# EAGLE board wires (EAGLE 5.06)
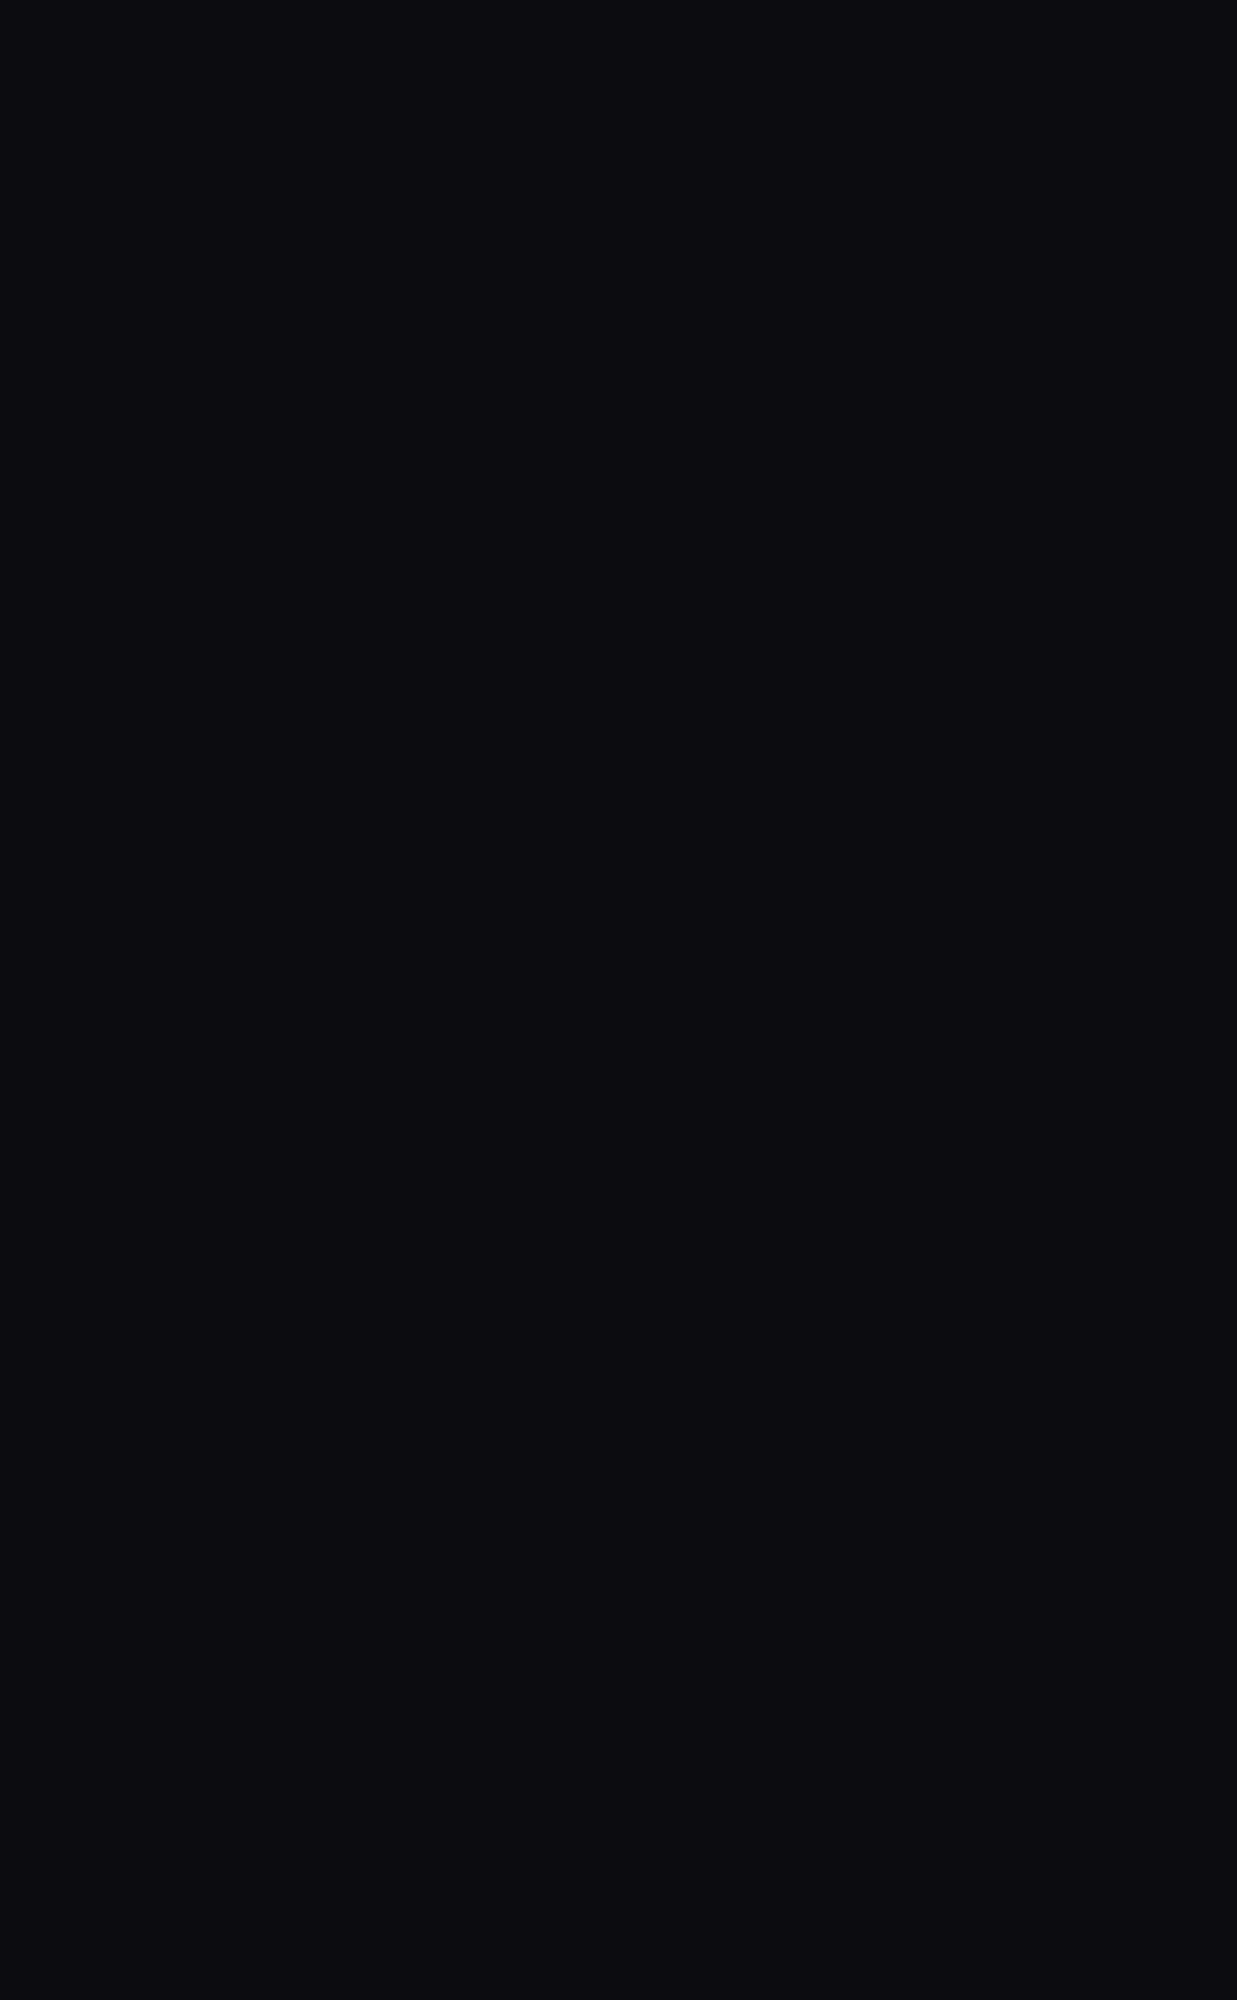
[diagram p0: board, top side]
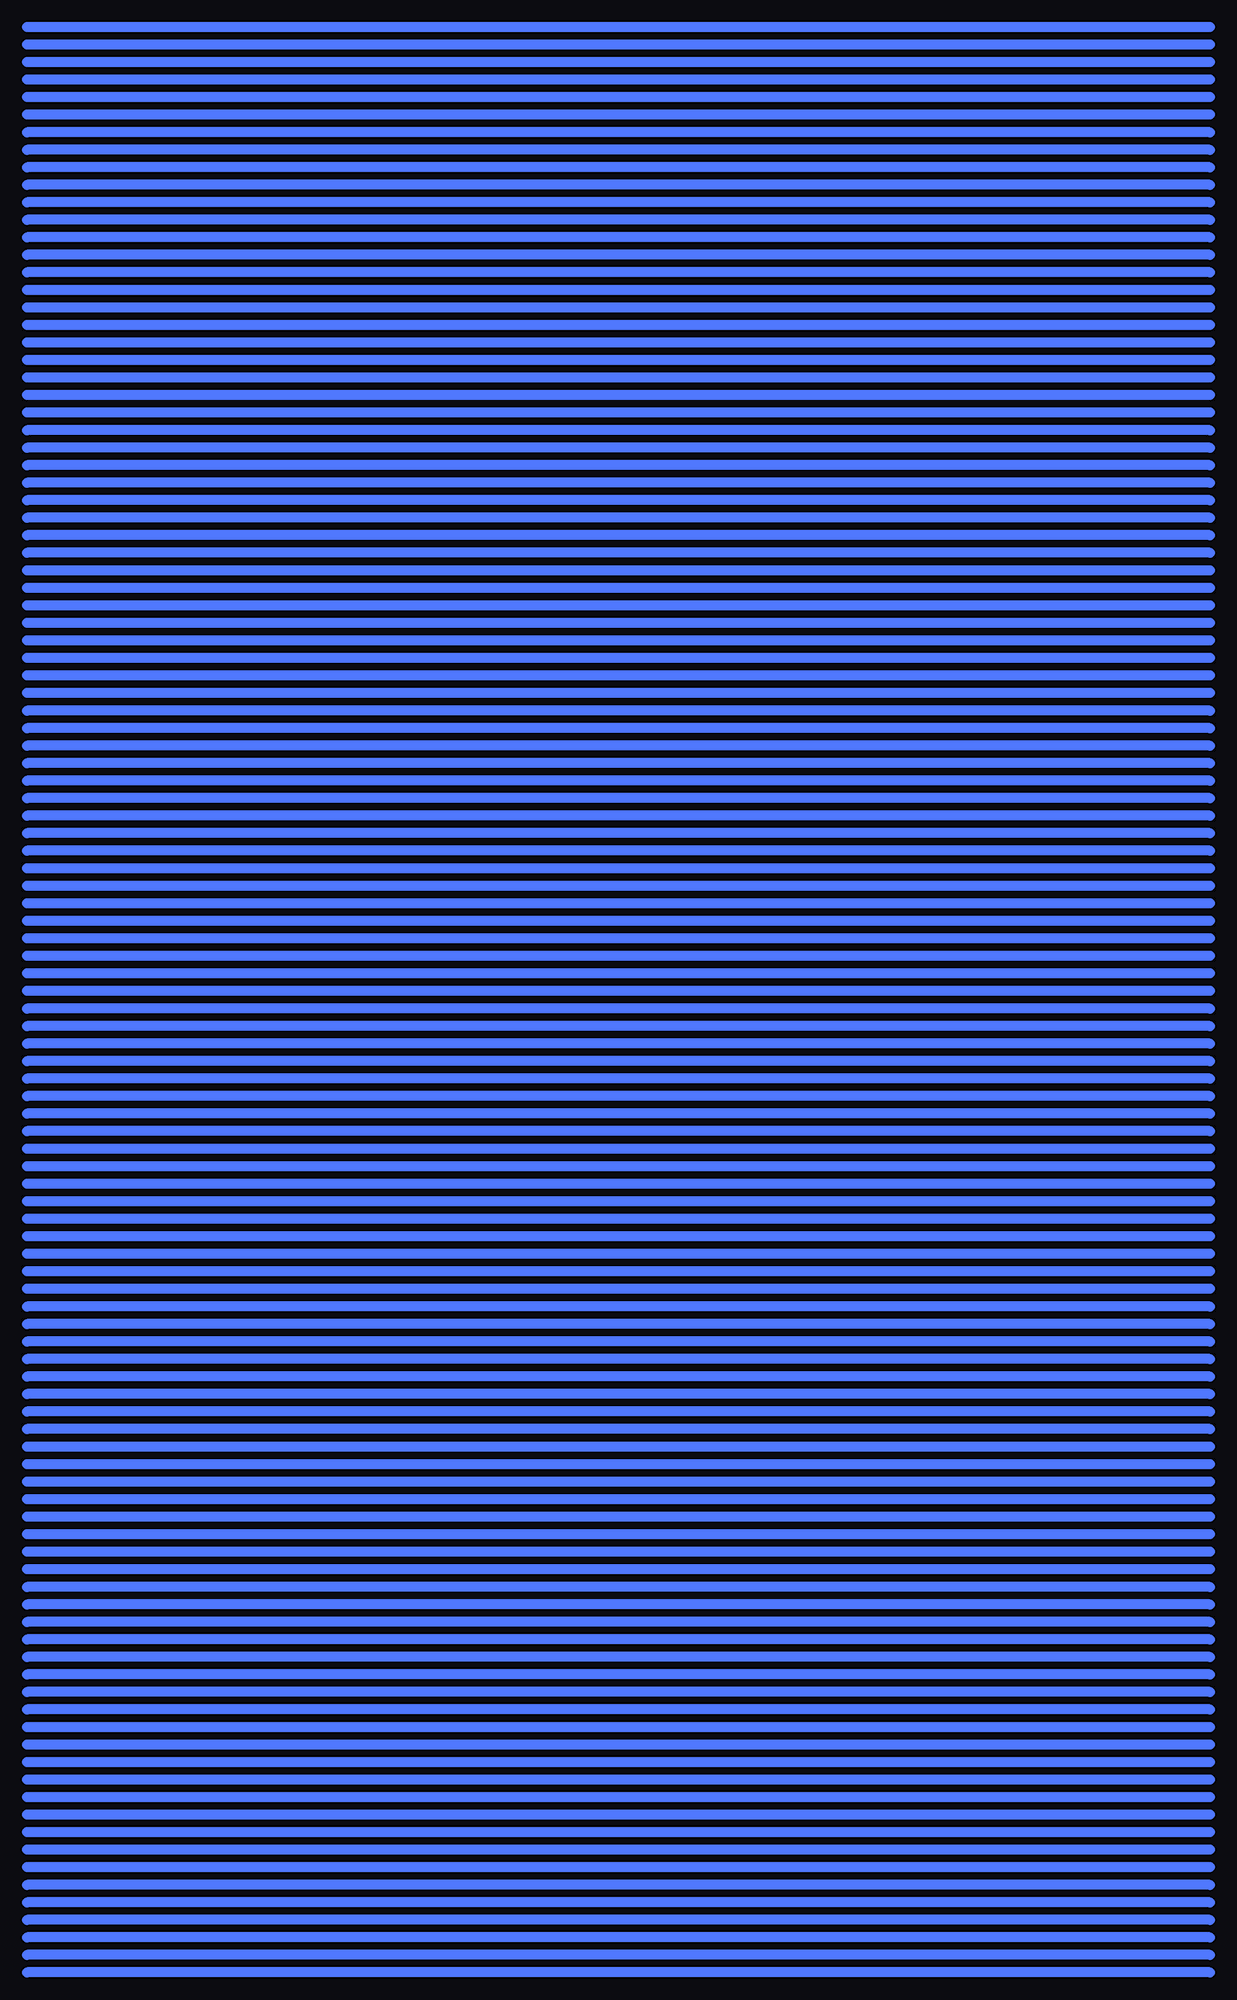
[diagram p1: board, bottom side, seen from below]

No outline drawn. Coordinates in mm, seen from the top.
Copper layers (1*16): Top 0.035mm / dielectric 1.5mm / Bottom 0.035mm
Design rules "default": minimum track width 10mil, minimum drill 24mil, track to track 8mil, track to pad 8mil, pad to pad 8mil, via to via 8mil, smd to smd 8mil, copper to edge 40mil, drill to drill 8mil, minimum pad ring 10mil, minimum via ring 8mil, stop-mask expansion 4mil, vias tented up to drill 0mil, thermal gap 10mil

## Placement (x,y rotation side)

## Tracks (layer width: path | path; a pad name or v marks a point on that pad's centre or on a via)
S$1
  Bottom 1.422: 0,0 171.45,0 | 0,2.54 171.45,2.54 | 0,5.08 171.45,5.08 | 0,15.24 171.45,15.24
S$2
  Bottom 1.422: 0,142.24 171.45,142.24 | 0,144.78 171.45,144.78 | 0,147.32 171.45,147.32 | 0,157.48 171.45,157.48
S$3
  Bottom 1.422: 0,7.62 171.45,7.62 | 0,10.16 171.45,10.16 | 0,12.7 171.45,12.7
S$4
  Bottom 1.422: 0,17.78 171.45,17.78 | 0,20.32 171.45,20.32 | 0,22.86 171.45,22.86 | 0,33.02 171.45,33.02
S$5
  Bottom 1.422: 0,25.4 171.45,25.4 | 0,27.94 171.45,27.94 | 0,30.48 171.45,30.48
S$6
  Bottom 1.422: 0,35.56 171.45,35.56 | 0,38.1 171.45,38.1 | 0,40.64 171.45,40.64 | 0,50.8 171.45,50.8
S$7
  Bottom 1.422: 0,43.18 171.45,43.18 | 0,45.72 171.45,45.72 | 0,48.26 171.45,48.26
S$8
  Bottom 1.422: 0,53.34 171.45,53.34 | 0,55.88 171.45,55.88 | 0,58.42 171.45,58.42 | 0,68.58 171.45,68.58
S$9
  Bottom 1.422: 0,60.96 171.45,60.96 | 0,63.5 171.45,63.5 | 0,66.04 171.45,66.04
S$10
  Bottom 1.422: 0,71.12 171.45,71.12 | 0,73.66 171.45,73.66 | 0,76.2 171.45,76.2 | 0,86.36 171.45,86.36
S$11
  Bottom 1.422: 0,78.74 171.45,78.74 | 0,81.28 171.45,81.28 | 0,83.82 171.45,83.82
S$12
  Bottom 1.422: 0,88.9 171.45,88.9 | 0,91.44 171.45,91.44 | 0,93.98 171.45,93.98 | 0,104.14 171.45,104.14
S$13
  Bottom 1.422: 0,96.52 171.45,96.52 | 0,99.06 171.45,99.06 | 0,101.6 171.45,101.6
S$14
  Bottom 1.422: 0,106.68 171.45,106.68 | 0,109.22 171.45,109.22 | 0,111.76 171.45,111.76 | 0,121.92 171.45,121.92
S$15
  Bottom 1.422: 0,114.3 171.45,114.3 | 0,116.84 171.45,116.84 | 0,119.38 171.45,119.38
S$16
  Bottom 1.422: 0,124.46 171.45,124.46 | 0,127 171.45,127 | 0,129.54 171.45,129.54 | 0,139.7 171.45,139.7
S$17
  Bottom 1.422: 0,132.08 171.45,132.08 | 0,134.62 171.45,134.62 | 0,137.16 171.45,137.16
S$18
  Bottom 1.422: 0,149.86 171.45,149.86 | 0,152.4 171.45,152.4 | 0,154.94 171.45,154.94
S$19
  Bottom 1.422: 0,160.02 171.45,160.02 | 0,162.56 171.45,162.56 | 0,165.1 171.45,165.1 | 0,175.26 171.45,175.26
S$20
  Bottom 1.422: 0,167.64 171.45,167.64 | 0,170.18 171.45,170.18 | 0,172.72 171.45,172.72
S$21
  Bottom 1.422: 0,177.8 171.45,177.8 | 0,180.34 171.45,180.34 | 0,182.88 171.45,182.88 | 0,193.04 171.45,193.04
S$22
  Bottom 1.422: 0,185.42 171.45,185.42 | 0,187.96 171.45,187.96 | 0,190.5 171.45,190.5
S$23
  Bottom 1.422: 0,195.58 171.45,195.58 | 0,198.12 171.45,198.12 | 0,200.66 171.45,200.66 | 0,210.82 171.45,210.82
S$24
  Bottom 1.422: 0,203.2 171.45,203.2 | 0,205.74 171.45,205.74 | 0,208.28 171.45,208.28
S$25
  Bottom 1.422: 0,213.36 171.45,213.36 | 0,215.9 171.45,215.9 | 0,218.44 171.45,218.44 | 0,228.6 171.45,228.6
S$26
  Bottom 1.422: 0,220.98 171.45,220.98 | 0,223.52 171.45,223.52 | 0,226.06 171.45,226.06
S$27
  Bottom 1.422: 0,231.14 171.45,231.14 | 0,233.68 171.45,233.68 | 0,236.22 171.45,236.22 | 0,246.38 171.45,246.38
S$28
  Bottom 1.422: 0,238.76 171.45,238.76 | 0,241.3 171.45,241.3 | 0,243.84 171.45,243.84
S$29
  Bottom 1.422: 0,248.92 171.45,248.92 | 0,251.46 171.45,251.46 | 0,254 171.45,254 | 0,264.16 171.45,264.16
S$30
  Bottom 1.422: 0,256.54 171.45,256.54 | 0,259.08 171.45,259.08 | 0,261.62 171.45,261.62
S$31
  Bottom 1.422: 0,266.7 171.45,266.7 | 0,269.24 171.45,269.24 | 0,271.78 171.45,271.78 | 0,281.94 171.45,281.94
S$32
  Bottom 1.422: 0,274.32 171.45,274.32 | 0,276.86 171.45,276.86 | 0,279.4 171.45,279.4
